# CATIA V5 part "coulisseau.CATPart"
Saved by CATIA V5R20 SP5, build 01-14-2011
Part number: coulisseau
Bounding box of the stored display mesh (mm): x -465.216 to -415.216, y -15 to 15, z -15 to 15
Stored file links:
  F:\iao\catia\projet iao\coulisseau.CATPart
  F:\iao\catia\projet iao\fhartmann.CATProduct
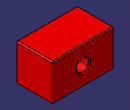
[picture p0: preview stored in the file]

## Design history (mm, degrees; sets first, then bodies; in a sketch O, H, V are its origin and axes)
External parameters (linked from other documents)
  External.coulisseau_longueur = 50 mm
  External.coulisseau_hauteur = 30 mm
  External.bielle_diametre_int = 10 mm
  External.coulisseau_largeur = 30 mm
Set1
  Plane1: linked copy from another document
  Point1 to Point3: linked copy from another document
Body1 (main body)
  Sketch1 on Plane1, origin (-440.2159, -187.1083, 0), H (0, 1, 0), V (0, 0, 1)
    line L1 (172.1083, 15) -> (202.1083, 15)
    line L2 (202.1083, 15) -> (202.1083, -15)
    line L3 (202.1083, -15) -> (172.1083, -15)
    line L4 (172.1083, -15) -> (172.1083, 15)
    point P2 (202.1083, 15)
    point P4 (172.1083, -15)
    reference projected point E1 (202.1083, 15) from Point1
    reference projected point E2 (172.1083, -15) from Point2
    distance L2 L4 = 30 {= External.coulisseau_hauteur}
    parallelism: L1 L3
    perpendicularity: L1 L4
    coincidence: P2 E1, P4 E2
  Pad1: profile Sketch1, direction (1, 0, 0), length 25 {= External.coulisseau_longueur /2}, opposite side length 25 {= External.coulisseau_longueur /2}
  Sketch2 on face of Pad1 from Sketch1.L2, origin (-29, 15, 0), H (1, 0, 0), V (0, 0, -1)
    point P1 (-411.2159, 0)
    reference projected point E1 (-411.2159, 0) from Point3
    coincidence: E1 P1
  Hole1: placed by Sketch2, at (-440.2159, 15, 0) direction (0, -1, 0), diameter 10 {= External.bielle_diametre_int}, depth 30 {= External.coulisseau_largeur}
  Chamfer1: length 1, angle 45, on edge [face of Pad1 from Sketch1.L1 | end face of Pad1]; edge [start face of Pad1 | face of Pad1 from Sketch1.L1]; edge [face of Pad1 from Sketch1.L4 | face of Pad1 from Sketch1.L1]; edge [face of Pad1 from Sketch1.L1 | face of Pad1 from Sketch1.L2]; edge [face of Pad1 from Sketch1.L2 | end face of Pad1]; edge [face of Pad1 from Sketch1.L4 | end face of Pad1]; edge [face of Pad1 from Sketch1.L3 | end face of Pad1]; edge [face of Pad1 from Sketch1.L2 | face of Pad1 from Sketch1.L3]; edge [face of Pad1 from Sketch1.L2 | face of Hole1]; edge [start face of Pad1 | face of Pad1 from Sketch1.L2]; edge [start face of Pad1 | face of Pad1 from Sketch1.L4]; edge [start face of Pad1 | face of Pad1 from Sketch1.L3]; edge [face of Pad1 from Sketch1.L3 | face of Pad1 from Sketch1.L4]; edge [face of Pad1 from Sketch1.L4 | face of Hole1]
